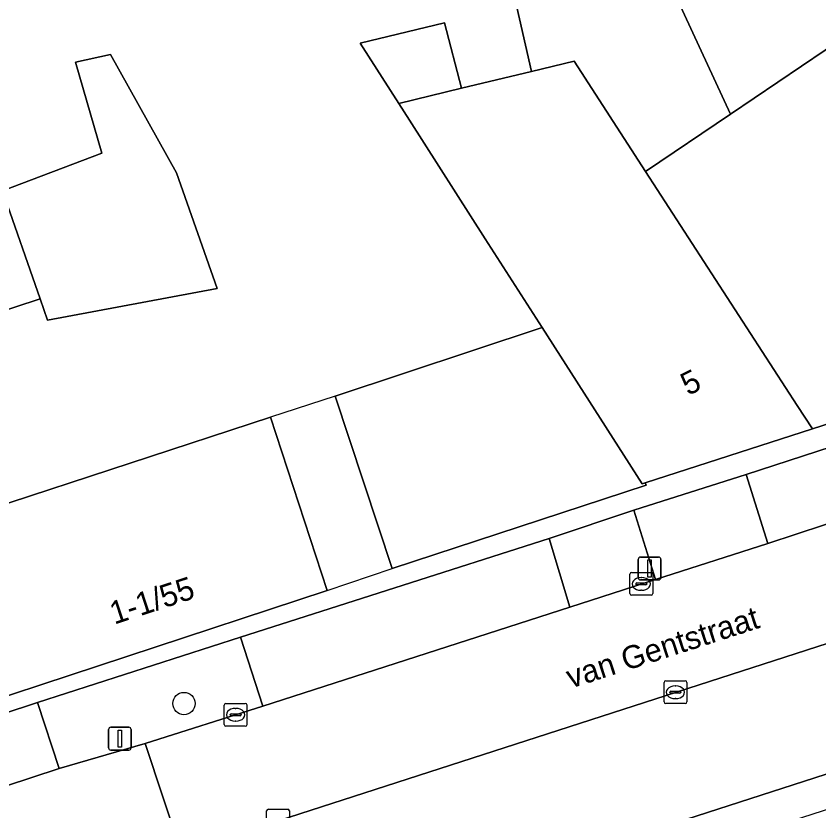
# Model space of a CAD drawing. Extents: x 160377 to 161131, y 383938 to 384853.
# Drawn here: x 160797.69 to 160832.91, y 384466.81 to 384501.67 of the extents above; entities that cross this region are included whole.
import ezdxf

# ---------------------------------------------------------------- set-up
doc = ezdxf.new("R2010")
doc.units = 0
for name, color, linetype in [('IMGEO_Boom', 7, 'Continuous'), ('IMGEO_Erf', 7, 'Continuous'), ('IMGEO_Kolk', 7, 'Continuous'), ('IMGEO_Lichtmast', 7, 'Continuous'), ('IMGEO_Openbare_ruimte_label', 7, 'Continuous'), ('IMGEO_Pand', 7, 'Continuous'), ('IMGEO_Pand_nummerreeks', 7, 'Continuous'), ('IMGEO_Pand_overbouw', 7, 'Continuous'), ('IMGEO_Parkeervlak_open', 7, 'Continuous'), ('IMGEO_Rijbaan_lokaal_open', 7, 'Continuous'), ('IMGEO_Voetpad_open', 7, 'Continuous')]:
    doc.layers.add(name, color=color, linetype=linetype)

msp = doc.modelspace()

# ---------------------------------------------------------------- linework, layer by layer
at = {"layer": 'IMGEO_Boom'}
msp.add_circle((160805.057, 384471.524), 0.489, dxfattribs=at)
at = {"layer": 'IMGEO_Erf'}
for points in [[(160839.119, 384514.345), (160832.071, 384512.67), (160831.983, 384513.038), (160831.529, 384514.948), (160829.089, 384514.368), (160829.39, 384513.101), (160827.108, 384512.558), (160827.915, 384509.164), (160828.448, 384506.924), (160824.985, 384506.101), (160829.021, 384497.374), (160835.248, 384501.579)], [(160846.142, 384487.924), (160832.619, 384483.568), (160825.289, 384481.206), (160825.325, 384481.095), (160814.191, 384477.443), (160811.688, 384485.009), (160820.761, 384488.019), (160818.273, 384491.908), (160814.947, 384497.107), (160814.475, 384497.844), (160812.789, 384500.48), (160816.483, 384501.37), (160817.233, 384498.508), (160820.294, 384499.246), (160818.527, 384507.023)], [(160797.102, 384494.005), (160801.454, 384495.663), (160800.299, 384499.643), (160801.833, 384499.987), (160804.728, 384494.794), (160806.512, 384489.723), (160799.068, 384488.338), (160798.745, 384489.268), (160790.827, 384486.663)], [(160796.529, 384480.04), (160808.852, 384484.086), (160811.339, 384476.476), (160793.75, 384470.688)], [(160793.931, 384470.022), (160798.636, 384471.562), (160807.529, 384474.432), (160821.067, 384478.764), (160824.789, 384479.999), (160829.712, 384481.568), (160833.445, 384482.788)]]:
    msp.add_lwpolyline(points, dxfattribs=at)
at = {"layer": 'IMGEO_Kolk'}
for p, q in [((160824.613, 384476.344), (160824.613, 384477.196)), ((160824.688, 384477.27), (160825.54, 384477.27)), ((160825.101, 384477.05), (160825.126, 384477.05)), ((160825.614, 384477.196), (160825.614, 384476.344)), ((160824.872, 384476.764), (160824.872, 384476.776)), ((160825.31, 384476.727), (160824.912, 384476.727)), ((160824.915, 384476.813), (160825.313, 384476.813)), ((160825.356, 384476.776), (160825.356, 384476.764)), ((160825.54, 384476.27), (160824.688, 384476.27)), ((160825.124, 384476.49), (160825.099, 384476.49)), ((160826.111, 384471.593), (160826.111, 384472.445)), ((160826.186, 384472.519), (160827.038, 384472.519)), ((160827.112, 384472.445), (160827.112, 384471.593)), ((160826.413, 384472.062), (160826.811, 384472.062)), ((160826.599, 384472.299), (160826.624, 384472.299)), ((160826.37, 384472.013), (160826.37, 384472.025)), ((160826.808, 384471.976), (160826.41, 384471.976)), ((160826.622, 384471.739), (160826.597, 384471.739)), ((160826.854, 384472.025), (160826.854, 384472.013)), ((160806.82, 384470.604), (160806.82, 384471.456)), ((160806.895, 384471.53), (160807.747, 384471.53)), ((160807.821, 384471.456), (160807.821, 384470.604)), ((160827.038, 384471.519), (160826.186, 384471.519)), ((160807.079, 384471.024), (160807.079, 384471.036)), ((160807.517, 384470.987), (160807.119, 384470.987)), ((160807.122, 384471.073), (160807.52, 384471.073)), ((160807.308, 384471.31), (160807.333, 384471.31)), ((160807.563, 384471.036), (160807.563, 384471.024)), ((160807.331, 384470.75), (160807.306, 384470.75)), ((160807.747, 384470.53), (160806.895, 384470.53)), ((160808.682, 384465.961), (160808.682, 384466.813)), ((160808.757, 384466.887), (160809.609, 384466.887)), ((160809.683, 384466.813), (160809.683, 384465.961))]:
    msp.add_line(p, q, dxfattribs=at)
for points in [[(160824.613, 384476.344), (160824.613, 384477.196)], [(160824.688, 384477.27), (160825.54, 384477.27)], [(160825.614, 384477.196), (160825.614, 384476.344)], [(160825.54, 384476.27), (160824.688, 384476.27)], [(160826.111, 384471.593), (160826.111, 384472.445)], [(160826.186, 384472.519), (160827.038, 384472.519)], [(160827.112, 384472.445), (160827.112, 384471.593)], [(160806.82, 384470.604), (160806.82, 384471.456)], [(160806.895, 384471.53), (160807.747, 384471.53)], [(160807.821, 384471.456), (160807.821, 384470.604)], [(160827.038, 384471.519), (160826.186, 384471.519)], [(160807.747, 384470.53), (160806.895, 384470.53)], [(160808.682, 384465.961), (160808.682, 384466.813)], [(160808.757, 384466.887), (160809.609, 384466.887)], [(160809.683, 384466.813), (160809.683, 384465.961)]]:
    msp.add_lwpolyline(points, dxfattribs=at)
for centre, radius, start, end in [((160824.69, 384477.194), 0.0765, 91.552, 178.448), ((160824.69, 384477.194), 0.0765, 91.552, 178.448), ((160825.538, 384477.194), 0.0765, 1.552, 88.448), ((160825.538, 384477.194), 0.0765, 1.552, 88.448), ((160824.912, 384476.773), 0.0403, 85.8775, 175.7526), ((160824.909, 384476.763), 0.0366, 178.938, 274.7102), ((160825.313, 384476.77), 0.043, 264.8664, 352.4533), ((160825.317, 384476.775), 0.0386, 1.7309, 96.639), ((160824.69, 384476.346), 0.0765, 181.552, 268.448), ((160824.69, 384476.346), 0.0765, 181.552, 268.448), ((160825.538, 384476.346), 0.0765, 271.552, 358.448), ((160825.538, 384476.346), 0.0765, 271.552, 358.448), ((160826.188, 384472.443), 0.0765, 91.552, 178.448), ((160826.188, 384472.443), 0.0765, 91.552, 178.448), ((160827.036, 384472.443), 0.0765, 1.552, 88.448), ((160827.036, 384472.443), 0.0765, 1.552, 88.448), ((160826.41, 384472.022), 0.0403, 85.8775, 175.7526), ((160826.815, 384472.024), 0.0386, 1.7309, 96.639), ((160826.407, 384472.012), 0.0366, 178.938, 274.7102), ((160826.811, 384472.019), 0.043, 264.8664, 352.4533), ((160806.897, 384471.454), 0.0765, 91.552, 178.448), ((160806.897, 384471.454), 0.0765, 91.552, 178.448), ((160807.745, 384471.454), 0.0765, 1.552, 88.448), ((160807.745, 384471.454), 0.0765, 1.552, 88.448), ((160826.188, 384471.595), 0.0765, 181.552, 268.448), ((160826.188, 384471.595), 0.0765, 181.552, 268.448), ((160827.036, 384471.595), 0.0765, 271.552, 358.448), ((160827.036, 384471.595), 0.0765, 271.552, 358.448), ((160807.119, 384471.033), 0.0403, 85.8775, 175.7526), ((160807.116, 384471.023), 0.0366, 178.938, 274.7102), ((160807.52, 384471.03), 0.043, 264.8664, 352.4533), ((160807.524, 384471.035), 0.0386, 1.7309, 96.639), ((160806.897, 384470.606), 0.0765, 181.552, 268.448), ((160806.897, 384470.606), 0.0765, 181.552, 268.448), ((160807.745, 384470.606), 0.0765, 271.552, 358.448), ((160807.745, 384470.606), 0.0765, 271.552, 358.448), ((160808.759, 384466.811), 0.0765, 91.552, 178.448), ((160808.759, 384466.811), 0.0765, 91.552, 178.448), ((160809.607, 384466.811), 0.0765, 1.552, 88.448), ((160809.607, 384466.811), 0.0765, 1.552, 88.448)]:
    msp.add_arc(centre, radius, start, end, dxfattribs=at)
for centre, major_axis, ratio, start_param, end_param in [((160825.1, 384476.77), (-0.387, 0.002), 0.722429, 4.712389, 7.853982), ((160825.125, 384476.77), (-0.39, 0.002), 0.717154, 1.570796, 4.712389), ((160826.598, 384472.019), (-0.387, 0.002), 0.722429, 4.712389, 7.853982), ((160826.623, 384472.019), (-0.39, 0.002), 0.717154, 1.570796, 4.712389), ((160807.307, 384471.03), (-0.387, 0.002), 0.722429, 4.712389, 7.853982), ((160807.332, 384471.03), (-0.39, 0.002), 0.717154, 1.570796, 4.712389)]:
    msp.add_ellipse(centre, major_axis=major_axis, ratio=ratio, start_param=start_param, end_param=end_param, dxfattribs=at)
at = {"layer": 'IMGEO_Lichtmast'}
for p, q in [((160824.984, 384477.045), (160824.984, 384477.845)), ((160824.984, 384477.845), (160824.984, 384477.045)), ((160825.084, 384477.945), (160825.874, 384477.945)), ((160825.874, 384477.945), (160825.084, 384477.945)), ((160825.974, 384477.845), (160825.974, 384477.045)), ((160825.974, 384477.045), (160825.974, 384477.845)), ((160825.874, 384476.945), (160825.084, 384476.945)), ((160825.084, 384476.945), (160825.874, 384476.945)), ((160801.748, 384469.581), (160801.748, 384470.381)), ((160801.748, 384470.381), (160801.748, 384469.581)), ((160801.848, 384470.481), (160802.638, 384470.481)), ((160802.638, 384470.481), (160801.848, 384470.481)), ((160802.738, 384470.381), (160802.738, 384469.581)), ((160802.738, 384469.581), (160802.738, 384470.381)), ((160802.638, 384469.481), (160801.848, 384469.481)), ((160801.848, 384469.481), (160802.638, 384469.481))]:
    msp.add_line(p, q, dxfattribs=at)
for points in [[(160825.404, 384477.82), (160825.554, 384477.82), (160825.554, 384477.07), (160825.404, 384477.07), (160825.404, 384477.82)], [(160802.168, 384470.356), (160802.318, 384470.356), (160802.318, 384469.606), (160802.168, 384469.606), (160802.168, 384470.356)]]:
    msp.add_lwpolyline(points, dxfattribs=at)
for centre, start, end in [((160825.084, 384477.845), 90, 180), ((160825.084, 384477.845), 90, 180), ((160825.874, 384477.845), 0, 90), ((160825.874, 384477.845), 360, 90), ((160825.084, 384477.045), 180, 270), ((160825.084, 384477.045), 180, 270), ((160825.874, 384477.045), 270, 0), ((160825.874, 384477.045), 270, 0), ((160801.848, 384470.381), 90, 180), ((160801.848, 384470.381), 90, 180), ((160802.638, 384470.381), 0, 90), ((160802.638, 384470.381), 360, 90), ((160801.848, 384469.581), 180, 270), ((160801.848, 384469.581), 180, 270), ((160802.638, 384469.581), 270, 0), ((160802.638, 384469.581), 270, 0)]:
    msp.add_arc(centre, 0.1, start, end, dxfattribs=at)
at = {"layer": 'IMGEO_Pand'}
for points in [[(160821.332, 384520.735), (160815.654, 384519.392), (160817.503, 384511.018), (160817.613, 384511.044), (160818.34, 384507.845), (160818.527, 384507.023), (160820.294, 384499.246), (160822.164, 384499.696), (160825.299, 384494.86), (160829.021, 384497.374), (160824.985, 384506.101), (160824.441, 384508.387), (160824.169, 384508.324)], [(160797.102, 384494.005), (160794.411, 384501.765), (160786.573, 384499.647), (160787.69, 384493.979), (160789.694, 384494.669), (160790.819, 384491.129), (160789.186, 384490.662), (160790.467, 384487.113), (160790.827, 384486.663), (160798.745, 384489.268)], [(160814.475, 384497.844), (160817.233, 384498.508), (160816.483, 384501.37), (160812.789, 384500.48)], [(160836.287, 384500), (160835.248, 384501.579), (160829.021, 384497.374), (160825.299, 384494.86), (160831.95, 384484.6), (160832.619, 384483.568), (160846.142, 384487.924), (160843.16, 384492.457), (160841.826, 384491.58)], [(160798.745, 384489.268), (160799.068, 384488.338), (160806.512, 384489.723), (160804.728, 384494.794), (160801.833, 384499.987), (160800.299, 384499.643), (160801.454, 384495.663), (160797.102, 384494.005)], [(160825.299, 384494.86), (160822.164, 384499.696), (160820.294, 384499.246), (160817.233, 384498.508), (160814.475, 384497.844), (160814.947, 384497.107), (160818.273, 384491.908), (160820.761, 384488.019), (160825.148, 384481.161), (160825.289, 384481.206), (160832.619, 384483.568), (160831.95, 384484.6)], [(160820.761, 384488.019), (160811.688, 384485.009), (160814.191, 384477.443), (160825.325, 384481.095), (160825.289, 384481.206), (160825.148, 384481.161)], [(160808.852, 384484.086), (160796.529, 384480.04), (160791.678, 384485.602), (160791.004, 384486.443), (160784.427, 384481.308), (160784.486, 384481.237), (160792.092, 384472.481), (160793.555, 384470.798), (160793.692, 384470.64), (160793.75, 384470.688), (160811.339, 384476.476)]]:
    msp.add_lwpolyline(points, close=True, dxfattribs=at)
at = {"layer": 'IMGEO_Pand_overbouw'}
msp.add_lwpolyline([(160811.688, 384485.009), (160808.852, 384484.086), (160811.339, 384476.476), (160814.191, 384477.443)], close=True, dxfattribs=at)
at = {"layer": 'IMGEO_Parkeervlak_open'}
for points in [[(160849.377, 384479.354), (160804.936, 384465.002)], [(160807.256, 384463.419), (160808.242, 384460.36), (160849.196, 384473.589), (160848.141, 384476.832)]]:
    msp.add_lwpolyline(points, dxfattribs=at)
at = {"layer": 'IMGEO_Rijbaan_lokaal_open'}
msp.add_lwpolyline([(160834.392, 384479.765), (160830.665, 384478.538), (160825.741, 384476.963), (160821.976, 384475.745), (160808.513, 384471.413), (160803.348, 384469.768), (160804.936, 384465.002), (160849.377, 384479.354)], dxfattribs=at)
at = {"layer": 'IMGEO_Voetpad_open'}
for points in [[(160803.348, 384469.768), (160799.588, 384468.677), (160794.903, 384467.137), (160793.931, 384470.022), (160793.804, 384469.999), (160793.555, 384470.798), (160792.092, 384472.481), (160784.486, 384481.237), (160784.427, 384481.308), (160781.728, 384484.55), (160775.613, 384492.483), (160770.824, 384498.232), (160768.624, 384509.5), (160768.147, 384511.974), (160767.765, 384514.068), (160765.465, 384513.637), (160764.851, 384513.492)], [(160848.141, 384476.832), (160849.196, 384473.589), (160808.242, 384460.36), (160808.598, 384458.923), (160844.65, 384470.556), (160852.393, 384473.054), (160852.23, 384473.351), (160857.703, 384476.351)], [(160804.936, 384465.002), (160803.348, 384469.768)]]:
    msp.add_lwpolyline(points, dxfattribs=at)
for points in [[(160829.712, 384481.568), (160830.665, 384478.538), (160834.392, 384479.765), (160833.445, 384482.788)], [(160824.789, 384479.999), (160825.741, 384476.963), (160830.665, 384478.538), (160829.712, 384481.568)], [(160821.067, 384478.764), (160821.976, 384475.745), (160825.741, 384476.963), (160824.789, 384479.999)], [(160821.976, 384475.745), (160821.067, 384478.764), (160807.529, 384474.432), (160808.513, 384471.413)], [(160803.348, 384469.768), (160808.513, 384471.413), (160807.529, 384474.432), (160798.636, 384471.562), (160799.588, 384468.677)], [(160799.588, 384468.677), (160798.636, 384471.562), (160793.931, 384470.022), (160794.903, 384467.137)]]:
    msp.add_lwpolyline(points, close=True, dxfattribs=at)

# ---------------------------------------------------------------- texts
at = {"layer": 'IMGEO_Openbare_ruimte_label'}
msp.add_text('van Gentstraat', height=1, rotation=17.8189, dxfattribs=at).set_placement((160822.018, 384472.175))
at = {"layer": 'IMGEO_Pand_nummerreeks'}
for s, rotation, p in [('5', 26.8202, (160827.166, 384485.005)), ('1-1/55', 18.2143, (160802.002, 384474.982))]:
    msp.add_text(s, height=1, rotation=rotation, dxfattribs=at).set_placement(p)

doc.saveas('drawing.dxf')
